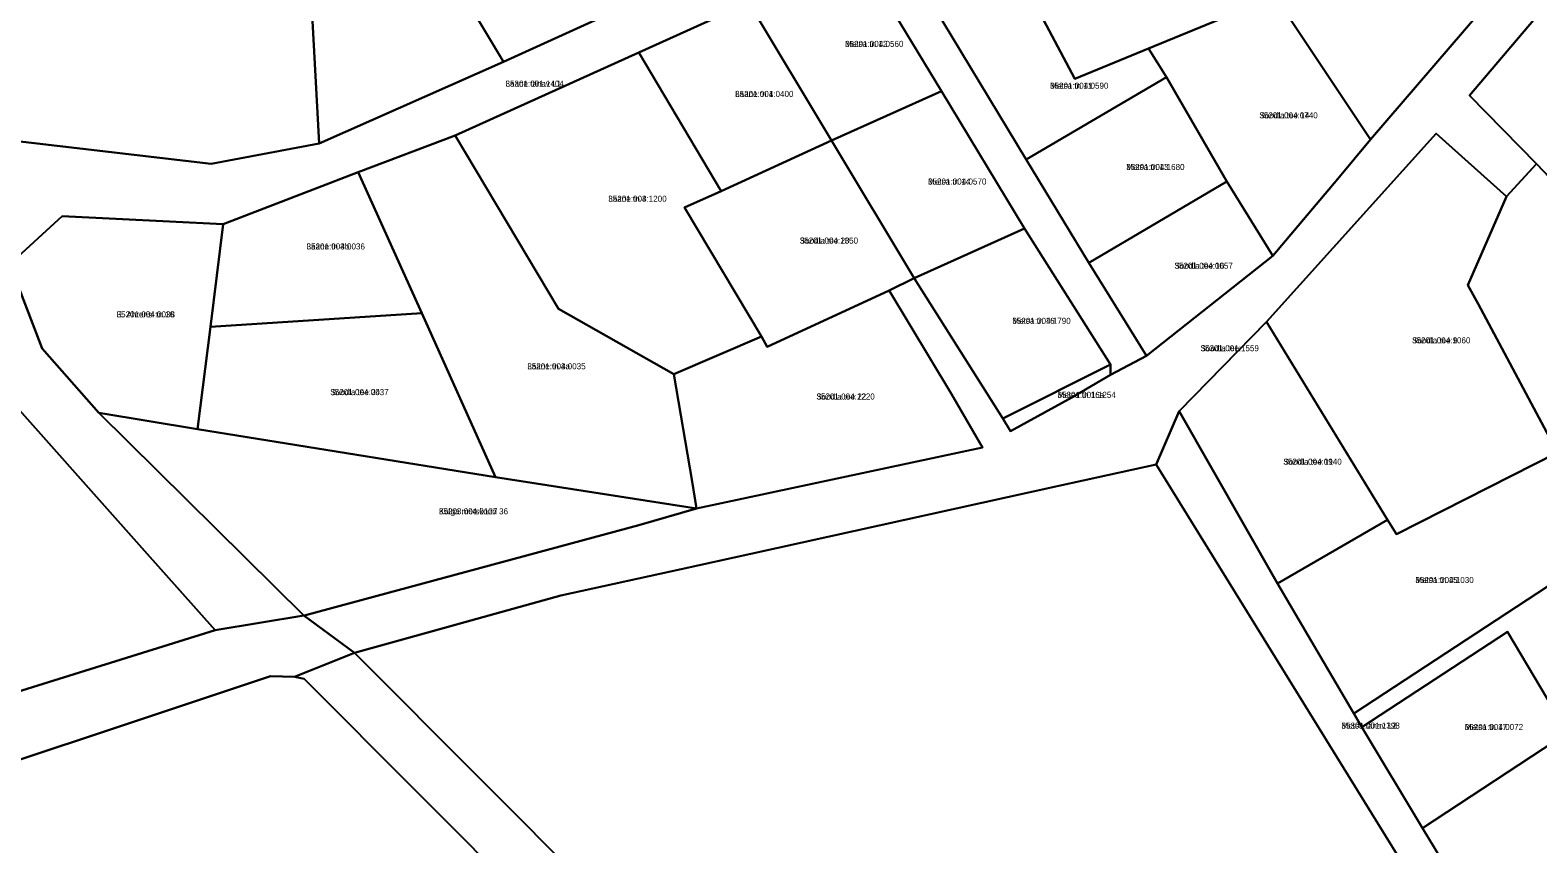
# Model space of a CAD drawing. Extents: x 570181 to 611446, y 6571894 to 6617855.
# Drawn here: x 581585 to 581959.8, y 6590200.9 to 6590403.2 of the extents above; entities that cross this region are included whole.
import ezdxf

# ---------------------------------------------------------------- set-up
doc = ezdxf.new("R2010")
doc.units = 0
for name, color, linetype in [('L_AADRESS', 7, 'Continuous'), ('PIIR', 7, 'Continuous'), ('TUNNUS', 7, 'Continuous')]:
    doc.layers.add(name, color=color, linetype=linetype)

msp = doc.modelspace()

# ---------------------------------------------------------------- linework, layer by layer
at = {"layer": 'PIIR'}
for points in [[(581633.32, 6590452.09), (581654.58, 6590417.8), (581656.86, 6590375.09), (581630, 6590370), (581579, 6590376), (581549, 6590389), (581518, 6590443), (581594, 6590452)], [(581681.82, 6590430.23), (581709.38, 6590442.01), (581710, 6590442.46), (581730.03, 6590407.79), (581702.66, 6590395.32)], [(581827.64, 6590423.36), (581840.84, 6590430.05), (581863.97, 6590442.79), (581871.66, 6590425.7), (581880.58, 6590405.87), (581863.02, 6590398.63), (581844.73, 6590391.16), (581828.48, 6590421.77)], [(581917.2, 6590442.96), (581945.64, 6590407.92), (581918.18, 6590376.04), (581894.34, 6590411.91), (581899.08, 6590426.71)], [(581549, 6590389), (581579, 6590376), (581630, 6590370), (581656.86, 6590375.09), (581702.66, 6590395.32), (581730.03, 6590407.79), (581757.57, 6590420.44), (581784.65, 6590433.34), (581790.85, 6590422.29), (581763.66, 6590410.02), (581736.3, 6590397.65), (581690.71, 6590377.01), (581666.55, 6590367.91), (581633.02, 6590354.98), (581592.97, 6590356.98), (581580.01, 6590345.03)], [(581656.86, 6590375.09), (581654.58, 6590417.8), (581681.82, 6590430.23), (581702.66, 6590395.32)], [(581942.83, 6590386.98), (581978.89, 6590429.48), (582001.33, 6590389.72), (581962.79, 6590366.54), (581959.49, 6590370.02)], [(581763.66, 6590410.02), (581790.85, 6590422.29), (581811.56, 6590388.1), (581784.25, 6590375.8)], [(581832.59, 6590371.07), (581809.61, 6590409.22), (581810.29, 6590411.89), (581828.48, 6590421.77), (581844.73, 6590391.16), (581863.02, 6590398.63), (581867.53, 6590391.51)], [(581763.66, 6590410.02), (581784.25, 6590375.8), (581756.8, 6590363.18), (581736.3, 6590397.65)], [(581882.47, 6590365.57), (581867.53, 6590391.51), (581863.02, 6590398.63), (581880.58, 6590405.87), (581885.16, 6590407.6), (581894.34, 6590411.91), (581918.18, 6590376.04), (581910.1, 6590366.26), (581893.92, 6590347.12)], [(581736.3, 6590397.65), (581756.8, 6590363.18), (581747.71, 6590359.17), (581766.8, 6590327.05), (581745.01, 6590317.69), (581716.37, 6590333.92), (581690.71, 6590377.01)], [(581832.59, 6590371.07), (581867.53, 6590391.51), (581882.47, 6590365.57), (581848.2, 6590345.42)], [(581804.79, 6590341.55), (581784.25, 6590375.8), (581811.56, 6590388.1), (581832.22, 6590353.92)], [(581666.55, 6590367.91), (581690.71, 6590377.01), (581716.37, 6590333.92), (581745.01, 6590317.69), (581749.56, 6590291), (581750.68, 6590284.3), (581700.71, 6590292.13), (581682.39, 6590332.84)], [(581922.44, 6590281.47), (581892.39, 6590330.68), (581900.61, 6590339.92), (581934.56, 6590377.53), (581952.03, 6590361.9), (581942.44, 6590339.85), (581944.95, 6590335.2), (581964.72, 6590298.24), (581924.69, 6590277.89)], [(581766.8, 6590327.05), (581747.71, 6590359.17), (581756.8, 6590363.18), (581784.25, 6590375.8), (581804.79, 6590341.55), (581798.57, 6590338.5), (581768.27, 6590324.53)], [(581944.95, 6590335.2), (581942.44, 6590339.85), (581952.03, 6590361.9), (581959.49, 6590370.02), (581962.79, 6590366.54), (581973.67, 6590355.27), (581980.92, 6590349.2), (581985.09, 6590329.08), (581999.66, 6590302.75), (582012.7, 6590279.15), (581999.82, 6590273.16), (581981.97, 6590266.33), (581977.35, 6590274.88), (581964.72, 6590298.24)], [(581633.02, 6590354.98), (581666.55, 6590367.91), (581682.39, 6590332.84), (581629.89, 6590329.51)], [(581848.2, 6590345.42), (581882.47, 6590365.57), (581893.92, 6590347.12), (581862.5, 6590322.26)], [(581580.01, 6590345.03), (581592.97, 6590356.98), (581633.02, 6590354.98), (581629.89, 6590329.51), (581626.66, 6590304.05), (581602.08, 6590308.06), (581588.05, 6590324.05)], [(581804.79, 6590341.55), (581832.22, 6590353.92), (581853.59, 6590320.11), (581826.78, 6590306.69)], [(581749.56, 6590291), (581745.01, 6590317.69), (581766.8, 6590327.05), (581768.27, 6590324.53), (581798.57, 6590338.5), (581814, 6590312.94), (581821.77, 6590299.49), (581750.68, 6590284.3)], [(581629.89, 6590329.51), (581682.39, 6590332.84), (581700.71, 6590292.13), (581626.66, 6590304.05)], [(581895.07, 6590265.69), (581870.68, 6590308.5), (581892.39, 6590330.68), (581922.44, 6590281.47)], [(581853.59, 6590320.11), (581853.54, 6590317.53), (581843.94, 6590311.9), (581828.7, 6590303.53), (581826.78, 6590306.69)], [(581348.73, 6590166.32), (581493.34, 6590263.99), (581575, 6590317), (581613.43, 6590273.81), (581631.04, 6590254.03), (581361.35, 6590169.97)], [(581864.9, 6590295.24), (581870.68, 6590308.5), (581895.07, 6590265.69), (581914.04, 6590233.34), (581916.1, 6590229.91), (581931.16, 6590204.84), (581957.1, 6590162.1), (581949.8, 6590157.87)], [(581653.81, 6590257.87), (581653.05, 6590257.67), (581602.08, 6590308.06), (581626.66, 6590304.05), (581700.71, 6590292.13), (581750.68, 6590284.3), (581736.3, 6590280.13)], [(581914.04, 6590233.34), (581895.07, 6590265.69), (581922.44, 6590281.47), (581924.69, 6590277.89), (581964.72, 6590298.24), (581977.35, 6590274.88)], [(581914.04, 6590233.34), (581977.35, 6590274.88), (581981.97, 6590266.33), (581983.89, 6590262.78), (581993.08, 6590245.54), (581967.2, 6590228.54), (581952.24, 6590253.63), (581916.1, 6590229.91)], [(581916.1, 6590229.91), (581952.24, 6590253.63), (581967.2, 6590228.54), (581931.16, 6590204.84)], [(581957.1, 6590162.1), (581931.16, 6590204.84), (581967.2, 6590228.54), (581993.08, 6590245.54), (582001.51, 6590227.68), (582004.1, 6590189.15)]]:
    msp.add_lwpolyline(points, close=True, dxfattribs=at)
for points in [[(581978.89, 6590429.48), (581942.83, 6590386.98), (581959.49, 6590370.02), (581952.03, 6590361.9), (581934.56, 6590377.53), (581900.61, 6590339.92), (581892.39, 6590330.68), (581870.68, 6590308.5), (581864.9, 6590295.24), (581840.72, 6590289.91), (581764.14, 6590273.04), (581746.89, 6590269.24), (581716.94, 6590262.64), (581665.63, 6590248.4), (581653.05, 6590257.67), (581653.81, 6590257.87), (581736.3, 6590280.13), (581750.68, 6590284.3), (581821.77, 6590299.49), (581814, 6590312.94), (581798.57, 6590338.5), (581804.79, 6590341.55), (581826.78, 6590306.69), (581828.7, 6590303.53), (581843.94, 6590311.9), (581853.54, 6590317.53), (581862.5, 6590322.26), (581893.92, 6590347.12), (581910.1, 6590366.26), (581918.18, 6590376.04), (581945.64, 6590407.92)], [(581809.61, 6590409.22), (581832.59, 6590371.07), (581848.2, 6590345.42), (581862.5, 6590322.26), (581853.54, 6590317.53), (581853.59, 6590320.11), (581832.22, 6590353.92), (581811.56, 6590388.1), (581790.85, 6590422.29)], [(581580.01, 6590345.03), (581588.05, 6590324.05), (581602.08, 6590308.06), (581653.05, 6590257.67), (581631.04, 6590254.03), (581613.43, 6590273.81), (581575, 6590317)], [(581957.91, 6589955.3), (581666.8, 6590247.23), (581665.63, 6590248.4), (581716.94, 6590262.64), (581746.89, 6590269.24), (581764.14, 6590273.04), (581840.72, 6590289.91), (581864.9, 6590295.24), (581949.8, 6590157.87)], [(581361.35, 6590169.97), (581631.04, 6590254.03), (581653.05, 6590257.67), (581665.63, 6590248.4), (581650.7, 6590242.5), (581644.78, 6590242.62), (581543.2, 6590208.8), (581481.42, 6590187.33)], [(582270.87, 6589605.49), (582207.8, 6589673.02), (582134.49, 6589751.09), (582054.55, 6589836.22), (581967.84, 6589928.55), (581850.15, 6590044.29), (581653.12, 6590241.96), (581650.7, 6590242.5), (581665.63, 6590248.4), (581666.8, 6590247.23), (581957.91, 6589955.3), (581961.71, 6589951.28), (582277.33, 6589617.17), (582287.69, 6589608.43), (582298.01, 6589599.73)], [(581481.42, 6590187.33), (581543.2, 6590208.8), (581644.78, 6590242.62), (581650.7, 6590242.5), (581653.12, 6590241.96), (581850.15, 6590044.29)]]:
    msp.add_lwpolyline(points, dxfattribs=at)

# ---------------------------------------------------------------- texts
at = {"layer": 'L_AADRESS'}
for s, p in [('Metsa tn 12', (581787.61, 6590399.07)), ('Laane tänav L1', (581703.19, 6590389.19)), ('Laane tn 1', (581760.27, 6590386.63)), ('Metsa tn 11', (581838.57, 6590388.67)), ('Soodla tee 14', (581890.6, 6590381.31)), ('Metsa tn 13', (581857.49, 6590368.47)), ('Metsa tn 14', (581808.23, 6590364.85)), ('Laane tn 3', (581728.75, 6590360.57)), ('Laane tn 3b', (581653.74, 6590348.71)), ('Soodla tee 20', (581776.34, 6590350.17)), ('Soodla tee 16', (581869.5, 6590343.92)), ('E. Ahrensi tn 16', (581606.52, 6590331.82)), ('Metsa tn 16', (581829.19, 6590330.22)), ('Soodla tee', (581875.97, 6590323.41)), ('Soodla tee 9', (581928.55, 6590325.37)), ('Laane tn 3a', (581708.61, 6590318.92)), ('Soodla tee 24', (581659.64, 6590312.49)), ('Soodla tee 22', (581780.49, 6590311.4)), ('Metsa tn 16a', (581840.41, 6590311.82)), ('Soodla tee 11', (581896.56, 6590295.2)), ('Kolga metskond 36', (581686.65, 6590282.87)), ('Metsa tn 15', (581929.37, 6590265.79)), ('Metsa tänav L2', (581911, 6590229.59)), ('Metsa tn 17', (581941.65, 6590229.24))]:
    msp.add_text(s, height=1.5, dxfattribs=at).set_placement(p)
at = {"layer": 'TUNNUS'}
for s, p in [('35201:004:0560', (581787.61, 6590399.07)), ('35301:001:1404', (581703.19, 6590389.19)), ('35201:004:0400', (581760.27, 6590386.63)), ('35201:004:0590', (581838.57, 6590388.67)), ('35201:004:0740', (581890.6, 6590381.31)), ('35201:004:1680', (581857.49, 6590368.47)), ('35201:004:0570', (581808.23, 6590364.85)), ('35201:004:1200', (581728.75, 6590360.57)), ('35201:004:0036', (581653.74, 6590348.71)), ('35201:004:1350', (581776.34, 6590350.17)), ('35201:004:0057', (581869.5, 6590343.92)), ('35201:004:0038', (581606.52, 6590331.82)), ('35201:004:1790', (581829.19, 6590330.22)), ('35301:001:1559', (581875.97, 6590323.41)), ('35201:004:1060', (581928.55, 6590325.37)), ('35201:004:0035', (581708.61, 6590318.92)), ('35201:004:0037', (581659.64, 6590312.49)), ('35201:004:1220', (581780.49, 6590311.4)), ('35301:001:1254', (581840.41, 6590311.82)), ('35201:004:0940', (581896.56, 6590295.2)), ('35203:004:0127', (581686.65, 6590282.87)), ('35201:004:1030', (581929.37, 6590265.79)), ('35301:001:1398', (581911, 6590229.59)), ('35201:004:0072', (581941.65, 6590229.24))]:
    msp.add_text(s, height=1.5, dxfattribs=at).set_placement(p)

doc.saveas('drawing.dxf')
